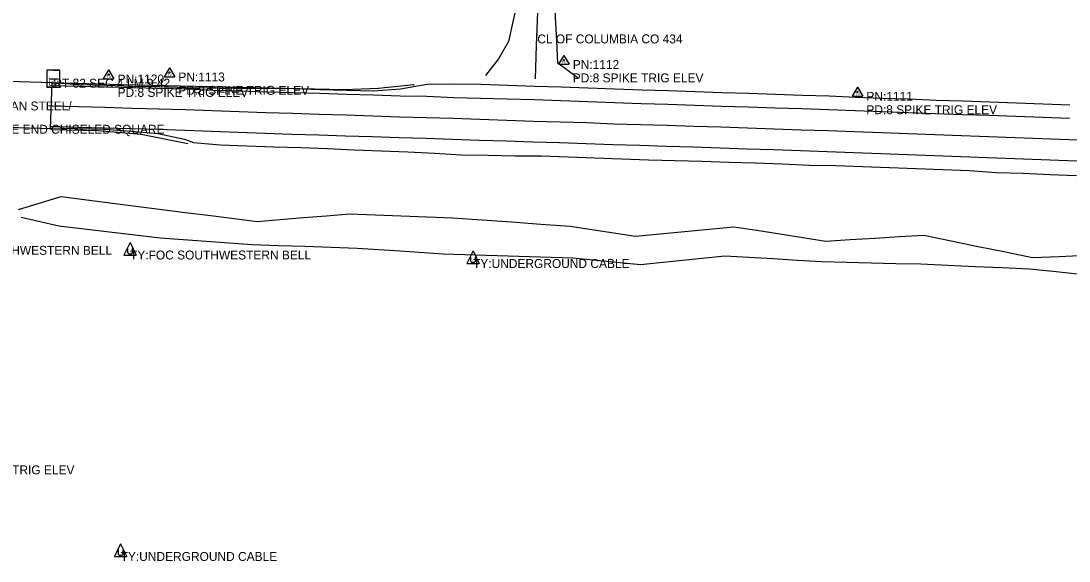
# Model space of a CAD drawing. Extents: x 976456 to 985170, y 1525951 to 1527080.
# Drawn here: x 978069 to 978656, y 1526238 to 1526541 of the extents above; entities that cross this region are included whole.
import ezdxf

# ---------------------------------------------------------------- set-up
doc = ezdxf.new("R2010")
doc.units = 0
for name, color, linetype in [('S_BRIDGE', 7, 'Continuous'), ('S_DITCHLINE', 7, 'Continuous'), ('S_EDGE_PAVEMENT', 7, 'Continuous'), ('S_GRAVEL_ROAD', 7, 'Continuous'), ('S_GUARDRAIL', 7, 'Continuous'), ('S_LOG_MILE', 7, 'Continuous'), ('S_LOG_MILE_ANNOT', 7, 'Continuous'), ('S_MSC_PT_SYM', 7, 'Continuous'), ('S_PAVEMENT_CROWN', 7, 'Continuous'), ('S_PRIMARY_CTL_ANNOT', 7, 'Continuous'), ('S_RDW_PT_SYM', 7, 'Continuous'), ('S_SECONDARY_CTL', 7, 'Continuous'), ('S_SECONDARY_CTL_ANNOT', 7, 'Continuous'), ('S_SHOULDER', 7, 'Continuous'), ('S_STR_PT_SYM', 7, 'Continuous'), ('S_SURVEY_TEXT_ANNOT', 7, 'Continuous'), ('S_UNDERGROUND_CABLE', 7, 'Continuous'), ('S_UTILITY_POLE_ANNOT', 7, 'Continuous')]:
    doc.layers.add(name, color=color, linetype=linetype)

msp = doc.modelspace()

# ---------------------------------------------------------------- linework, layer by layer
at = {"layer": 'S_BRIDGE'}
for p, q in [((978086.33, 1526506.14), (977956.8, 1526510.36)), ((978085.38, 1526480.48), (978086.33, 1526506.14)), ((977955.86, 1526484.94), (978085.38, 1526480.48))]:
    msp.add_line(p, q, dxfattribs=at)
at = {"layer": 'S_DITCHLINE'}
for points in [[(978665.19, 1526409.37), (978650.29, 1526408.71), (978635.4, 1526408.06), (978620.19, 1526411.2), (978604.99, 1526414.35), (978589.78, 1526417.49), (978574.58, 1526420.64), (978560.82, 1526419.8), (978547.07, 1526418.97), (978533.32, 1526418.14), (978519.57, 1526417.3), (978506.68, 1526419.31), (978493.79, 1526421.32), (978480.9, 1526423.33), (978468.01, 1526425.35), (978454.27, 1526424.02), (978440.53, 1526422.7), (978426.8, 1526421.37), (978413.06, 1526420.05), (978394.71, 1526422.87), (978376.37, 1526425.69), (978359.92, 1526426.86), (978343.46, 1526428.03), (978327.01, 1526429.2), (978310.56, 1526430.37), (978296.1, 1526430.93), (978281.65, 1526431.48), (978267.19, 1526432.04), (978252.74, 1526432.59), (978239.84, 1526431.52), (978226.93, 1526430.44), (978214.03, 1526429.36), (978201.13, 1526428.28), (978188.15, 1526429.91), (978175.16, 1526431.55), (978162.18, 1526433.18), (978149.19, 1526434.82), (978134.66, 1526436.69), (978120.12, 1526438.57), (978105.59, 1526440.44), (978091.05, 1526442.31), (978067.19, 1526434.95)], [(978663.72, 1526398.58), (978648.71, 1526400.19), (978633.71, 1526401.8), (978618.47, 1526402.48), (978603.24, 1526403.15), (978588.01, 1526403.82), (978572.78, 1526404.49), (978558.9, 1526404.83), (978545.02, 1526405.17), (978531.15, 1526405.51), (978517.27, 1526405.84), (978503.69, 1526406.65), (978490.12, 1526407.46), (978476.54, 1526408.26), (978462.96, 1526409.06), (978439.36, 1526406.58), (978415.76, 1526404.1), (978396.8, 1526405.97), (978377.85, 1526407.85), (978359.69, 1526408.43), (978341.54, 1526409.01), (978323.38, 1526409.59), (978305.23, 1526410.17), (978281.18, 1526411.77), (978257.12, 1526413.36), (978242.43, 1526413.88), (978227.73, 1526414.39), (978213.04, 1526414.91), (978198.34, 1526415.43), (978185.42, 1526416.34), (978172.5, 1526417.25), (978159.58, 1526418.16), (978146.65, 1526419.07), (978132.48, 1526420.77), (978118.31, 1526422.48), (978104.14, 1526424.18), (978089.97, 1526425.88), (978068.85, 1526430.74)]]:
    msp.add_lwpolyline(points, dxfattribs=at)
at = {"layer": 'S_EDGE_PAVEMENT'}
for points in [[(978086.37, 1526504.73), (978101.36, 1526504.3), (978116.36, 1526503.94), (978131.36, 1526503.46), (978146.36, 1526503.14), (978161.36, 1526502.8), (978176.34, 1526502.14), (978191.34, 1526501.73), (978206.33, 1526501.17), (978221.32, 1526500.71), (978236.19, 1526500.3), (978251.18, 1526499.88), (978266.18, 1526499.47), (978281.17, 1526498.96), (978296.16, 1526498.61), (978311.15, 1526498.02), (978326.18, 1526497.61), (978341.17, 1526497.18), (978356.17, 1526496.74), (978371.16, 1526496.3), (978386.23, 1526495.68), (978401.22, 1526495.14), (978416.21, 1526494.62), (978431.19, 1526494.29), (978446.18, 1526493.67), (978461.17, 1526493.16), (978476.16, 1526492.73), (978491.15, 1526492.23), (978506.14, 1526491.72), (978506.14, 1526491.72), (978521.14, 1526491.22), (978536.12, 1526490.57), (978551.11, 1526490.06), (978566.1, 1526489.56), (978581.09, 1526488.97), (978581.09, 1526488.97), (978596.12, 1526488.42), (978611.12, 1526487.99), (978626.11, 1526487.44), (978641.1, 1526486.88), (978656.09, 1526486.41)], [(978085.55, 1526481.83), (978100.54, 1526481.36), (978115.54, 1526480.97), (978130.52, 1526480.56), (978145.52, 1526480.14), (978145.52, 1526480.14), (978160.51, 1526479.59), (978175.5, 1526479.08), (978190.49, 1526478.52), (978190.49, 1526478.52), (978205.48, 1526477.96), (978220.47, 1526477.44), (978235.56, 1526476.98), (978250.55, 1526476.52), (978265.55, 1526476.07), (978280.54, 1526475.59), (978295.53, 1526475.09), (978310.52, 1526474.56), (978325.49, 1526474.11), (978340.49, 1526473.68), (978355.48, 1526473.18), (978370.47, 1526472.7), (978370.47, 1526472.7), (978385.39, 1526472.21), (978400.38, 1526471.68), (978415.38, 1526471.17), (978430.39, 1526470.66), (978445.38, 1526470.21), (978460.37, 1526469.72), (978475.36, 1526469.25), (978475.36, 1526469.25), (978490.35, 1526468.73), (978505.34, 1526468.18), (978520.34, 1526467.68), (978520.34, 1526467.68), (978535.33, 1526467.17), (978550.32, 1526466.62), (978565.31, 1526466.05), (978580.3, 1526465.46), (978595.25, 1526464.85), (978610.24, 1526464.24), (978625.23, 1526463.76), (978625.23, 1526463.76), (978640.22, 1526463.24), (978640.22, 1526463.24), (978655.21, 1526462.69), (978655.21, 1526462.69), (978670.21, 1526462.19)]]:
    msp.add_lwpolyline(points, dxfattribs=at)
at = {"layer": 'S_GRAVEL_ROAD'}
for points in [[(978361.37, 1526856.47), (978359.38, 1526794.04), (978358.93, 1526780.06), (978358.49, 1526766.07), (978358.04, 1526752.09), (978357.2, 1526736.65), (978356.36, 1526721.22), (978355.52, 1526705.79), (978354.68, 1526690.35), (978354.79, 1526670.11), (978354.9, 1526649.86), (978352.93, 1526629.69), (978350.96, 1526609.51), (978349.95, 1526587.81), (978348.71, 1526571.32), (978347.48, 1526554.83), (978344.69, 1526542.11), (978341.91, 1526529.4), (978336.32, 1526519.7), (978328.9, 1526510.25)], [(978381.06, 1526508.64), (978369.53, 1526517.1), (978368.86, 1526529.94), (978368.19, 1526542.79), (978368.22, 1526555.92), (978368.26, 1526569.05), (978369.23, 1526584.52), (978369.8, 1526604.85), (978370.36, 1526625.19), (978370.83, 1526641.45), (978371.3, 1526657.71), (978371.76, 1526673.97), (978372.23, 1526690.23), (978372.7, 1526702.89), (978373.18, 1526715.55), (978373.65, 1526728.21), (978374.13, 1526740.87), (978374.79, 1526756.83), (978375.46, 1526772.79), (978376.12, 1526788.75), (978378.92, 1526855.74)]]:
    msp.add_lwpolyline(points, dxfattribs=at)
at = {"layer": 'S_GUARDRAIL'}
for p, q in [((978125, 1526505.12), (978086.41, 1526506.23)), ((978249.95, 1526502.28), (978125, 1526505.12)), ((978268.85, 1526502.92), (978249.95, 1526502.28)), ((978288.78, 1526504.99), (978268.85, 1526502.92)), ((978086, 1526480.02), (978111.99, 1526479.4)), ((978111.99, 1526479.4), (978136.01, 1526477.42)), ((978136.01, 1526477.42), (978162.25, 1526472.18))]:
    msp.add_line(p, q, dxfattribs=at)
at = {"layer": 'S_LOG_MILE'}
for p, q in [((978086.9, 1526513.25), (978090.5, 1526513.25)), ((978084.5, 1526508.45), (978089.3, 1526508.45)), ((978086.9, 1526503.65), (978083.3, 1526503.65))]:
    msp.add_line(p, q, dxfattribs=at)
msp.add_lwpolyline([(978090.5, 1526513.25), (978083.3, 1526513.25), (978083.3, 1526503.65), (978090.5, 1526503.65)], close=True, dxfattribs=at)
at = {"layer": 'S_MSC_PT_SYM'}
msp.add_lwpolyline([(978357.98, 1526533.25), (978357.98, 1526533.3), (978357.98, 1526533.25), (978357.93, 1526533.25), (978357.98, 1526533.25), (978357.98, 1526533.2), (978357.98, 1526533.25), (978358.03, 1526533.25)], dxfattribs=at)
at = {"layer": 'S_PAVEMENT_CROWN'}
for points in [[(978356.9, 1526508.47), (978357.57, 1526527.13), (978358.24, 1526545.8), (978359.35, 1526558.49), (978360.47, 1526571.19), (978360.67, 1526585.26), (978361.11, 1526605.62), (978361.56, 1526625.97), (978362.65, 1526642.09), (978363.74, 1526658.21), (978364.83, 1526674.33), (978365.92, 1526690.45), (978366.17, 1526703.09), (978366.42, 1526715.74), (978366.67, 1526728.38), (978366.92, 1526741.02), (978367.64, 1526757.28), (978368.35, 1526773.54), (978369.07, 1526789.8), (978369.78, 1526806.07)], [(978085.96, 1526493.34), (978100.96, 1526492.95), (978115.95, 1526492.5), (978130.94, 1526491.98), (978145.94, 1526491.6), (978160.94, 1526491.22), (978160.94, 1526491.22), (978175.93, 1526490.67), (978175.93, 1526490.67), (978190.92, 1526490.13), (978190.92, 1526490.13), (978205.91, 1526489.6), (978220.9, 1526489.07), (978235.87, 1526488.65), (978250.87, 1526488.15), (978265.86, 1526487.65), (978265.86, 1526487.65), (978280.85, 1526487.19), (978295.84, 1526486.71), (978310.84, 1526486.31), (978310.84, 1526486.31), (978325.83, 1526485.87), (978325.83, 1526485.87), (978340.83, 1526485.33), (978355.82, 1526484.76), (978355.82, 1526484.76), (978370.81, 1526484.32), (978370.81, 1526484.32), (978385.81, 1526483.85), (978385.81, 1526483.85), (978400.8, 1526483.25), (978415.79, 1526482.8), (978415.79, 1526482.8), (978430.79, 1526482.44), (978445.78, 1526481.92), (978445.78, 1526481.92), (978460.77, 1526481.45), (978475.76, 1526480.94), (978475.76, 1526480.94), (978490.75, 1526480.43), (978505.74, 1526479.9), (978520.73, 1526479.39), (978520.73, 1526479.39), (978535.72, 1526478.89), (978550.72, 1526478.38), (978565.71, 1526477.86), (978580.7, 1526477.27), (978595.69, 1526476.72), (978610.68, 1526476.04), (978610.68, 1526476.04), (978625.67, 1526475.53), (978640.66, 1526474.97), (978640.66, 1526474.97), (978655.65, 1526474.42), (978655.65, 1526474.42), (978670.64, 1526473.94)]]:
    msp.add_lwpolyline(points, dxfattribs=at)
at = {"layer": 'S_RDW_PT_SYM'}
for points in [[(978086.41, 1526506.23), (978086.41, 1526506.28), (978086.41, 1526506.23), (978086.36, 1526506.23), (978086.41, 1526506.23), (978086.41, 1526506.18), (978086.41, 1526506.23), (978086.46, 1526506.23)], [(978125, 1526505.12), (978125, 1526505.17), (978125, 1526505.12), (978124.95, 1526505.12), (978125, 1526505.12), (978125, 1526505.07), (978125, 1526505.12), (978125.05, 1526505.12)], [(978249.95, 1526502.28), (978249.95, 1526502.33), (978249.95, 1526502.28), (978249.9, 1526502.28), (978249.95, 1526502.28), (978249.95, 1526502.23), (978249.95, 1526502.28), (978250, 1526502.28)], [(978268.85, 1526502.92), (978268.85, 1526502.97), (978268.85, 1526502.92), (978268.8, 1526502.92), (978268.85, 1526502.92), (978268.85, 1526502.87), (978268.85, 1526502.92), (978268.9, 1526502.92)], [(978288.78, 1526504.99), (978288.78, 1526505.04), (978288.78, 1526504.99), (978288.73, 1526504.99), (978288.78, 1526504.99), (978288.78, 1526504.94), (978288.78, 1526504.99), (978288.83, 1526504.99)], [(978086, 1526480.02), (978086, 1526480.07), (978086, 1526480.02), (978085.95, 1526480.02), (978086, 1526480.02), (978086, 1526479.97), (978086, 1526480.02), (978086.05, 1526480.02)], [(978111.99, 1526479.4), (978111.99, 1526479.45), (978111.99, 1526479.4), (978111.94, 1526479.4), (978111.99, 1526479.4), (978111.99, 1526479.35), (978111.99, 1526479.4), (978112.04, 1526479.4)], [(978136.01, 1526477.42), (978136.01, 1526477.47), (978136.01, 1526477.42), (978135.96, 1526477.42), (978136.01, 1526477.42), (978136.01, 1526477.37), (978136.01, 1526477.42), (978136.06, 1526477.42)], [(978162.25, 1526472.18), (978162.25, 1526472.23), (978162.25, 1526472.18), (978162.2, 1526472.18), (978162.25, 1526472.18), (978162.25, 1526472.13), (978162.25, 1526472.18), (978162.3, 1526472.18)]]:
    msp.add_lwpolyline(points, dxfattribs=at)
at = {"layer": 'S_SECONDARY_CTL'}
for p, q in [((978372.85, 1526521.53), (978369.84, 1526516.57)), ((978372.85, 1526521.53), (978375.79, 1526516.57)), ((978117.88, 1526513.42), (978114.87, 1526508.47)), ((978117.88, 1526513.42), (978120.83, 1526508.47)), ((978151.91, 1526514.56), (978148.9, 1526509.61)), ((978151.91, 1526514.56), (978154.86, 1526509.61)), ((978369.84, 1526516.57), (978375.79, 1526516.57)), ((978114.87, 1526508.47), (978120.83, 1526508.47)), ((978148.9, 1526509.61), (978154.86, 1526509.61)), ((978537.31, 1526503.71), (978534.3, 1526498.75)), ((978537.31, 1526503.71), (978540.26, 1526498.75)), ((978534.3, 1526498.75), (978540.26, 1526498.75))]:
    msp.add_line(p, q, dxfattribs=at)
for centre, radius in [((978372.85, 1526518.92), 0.311), ((978372.85, 1526518.92), 0.183), ((978372.85, 1526518.92), 0.103), ((978117.88, 1526510.81), 0.311), ((978117.88, 1526510.81), 0.183), ((978117.88, 1526510.81), 0.103), ((978151.91, 1526511.95), 0.311), ((978151.91, 1526511.95), 0.183), ((978151.91, 1526511.95), 0.103), ((978537.31, 1526501.1), 0.311), ((978537.31, 1526501.1), 0.183), ((978537.31, 1526501.1), 0.103)]:
    msp.add_circle(centre, radius, dxfattribs=at)
at = {"layer": 'S_SHOULDER'}
for points in [[(978086.43, 1526506.26), (978101.4, 1526505.26), (978116.4, 1526504.89), (978131.4, 1526504.36), (978146.4, 1526504.05), (978161.39, 1526503.6), (978176.4, 1526503.39), (978191.4, 1526503.23), (978206.41, 1526503.21), (978221.41, 1526503.01), (978236.25, 1526502.42), (978251.24, 1526502), (978266.24, 1526501.59), (978281.28, 1526502.85), (978296.35, 1526505.34), (978311.37, 1526505.69), (978326.41, 1526505.35), (978341.4, 1526504.81), (978356.39, 1526504.38), (978371.39, 1526503.94), (978386.51, 1526503.29), (978401.5, 1526502.75), (978416.49, 1526502.18), (978431.45, 1526501.84), (978446.44, 1526501.26), (978461.43, 1526500.77), (978476.43, 1526500.34), (978491.42, 1526499.84), (978506.41, 1526499.33), (978521.4, 1526498.79), (978536.39, 1526498.14), (978551.38, 1526497.63), (978566.37, 1526497.16), (978581.36, 1526496.54), (978596.41, 1526495.99), (978611.4, 1526495.56), (978626.39, 1526494.98), (978641.38, 1526494.37), (978656.37, 1526493.9)], [(978085.51, 1526481.03), (978100.5, 1526480.55), (978115.5, 1526480.14), (978130.46, 1526479.08), (978145.42, 1526477.81), (978160.31, 1526474.55), (978165.4, 1526472.81), (978180.36, 1526471.48), (978195.35, 1526470.84), (978210.34, 1526470.29), (978225.5, 1526469.84), (978240.49, 1526469.39), (978255.48, 1526468.65), (978270.47, 1526468.02), (978285.46, 1526467.51), (978300.44, 1526466.67), (978315.38, 1526465.86), (978330.39, 1526465.66), (978345.38, 1526465.29), (978360.38, 1526465.18), (978375.26, 1526464.78), (978390.24, 1526464.15), (978405.24, 1526463.63), (978420.26, 1526463.09), (978435.26, 1526462.73), (978450.25, 1526462.28), (978465.24, 1526461.76), (978480.23, 1526461.31), (978495.22, 1526460.73), (978510.21, 1526460.05), (978525.21, 1526459.79), (978540.2, 1526459.34), (978555.19, 1526458.77), (978570.18, 1526458.21), (978585.12, 1526457.67), (978600.1, 1526457.01), (978615.08, 1526455.98), (978630.07, 1526455.58), (978645.05, 1526454.87), (978660.04, 1526454.15)]]:
    msp.add_lwpolyline(points, dxfattribs=at)
at = {"layer": 'S_STR_PT_SYM'}
for points in [[(978086.33, 1526506.14), (978086.33, 1526506.64), (978086.33, 1526506.14), (978085.83, 1526506.14), (978086.33, 1526506.14), (978086.33, 1526505.64), (978086.33, 1526506.14), (978086.83, 1526506.14)], [(978085.38, 1526480.48), (978085.38, 1526480.98), (978085.38, 1526480.48), (978084.88, 1526480.48), (978085.38, 1526480.48), (978085.38, 1526479.98), (978085.38, 1526480.48), (978085.88, 1526480.48)]]:
    msp.add_lwpolyline(points, dxfattribs=at)
at = {"layer": 'S_UNDERGROUND_CABLE'}
for p, q in [((978129.86, 1526416.73), (978126.34, 1526409.64)), ((978128.66, 1526410.88), (978128.66, 1526413.32)), ((978129.86, 1526416.73), (978133.35, 1526409.64)), ((978131.03, 1526413.32), (978131.03, 1526410.88)), ((978126.34, 1526409.64), (978133.35, 1526409.64)), ((978129.28, 1526410.22), (978128.66, 1526410.88)), ((978130.48, 1526410.22), (978129.28, 1526410.22)), ((978131.03, 1526410.88), (978130.48, 1526410.22)), ((978321.98, 1526411.94), (978318.45, 1526404.85)), ((978320.78, 1526406.09), (978320.78, 1526408.53)), ((978321.98, 1526411.94), (978325.46, 1526404.85)), ((978323.14, 1526408.53), (978323.14, 1526406.09)), ((978318.45, 1526404.85), (978325.46, 1526404.85)), ((978321.4, 1526405.43), (978320.78, 1526406.09)), ((978322.6, 1526405.43), (978321.4, 1526405.43)), ((978323.14, 1526406.09), (978322.6, 1526405.43)), ((978124.6, 1526247.81), (978121.08, 1526240.72)), ((978123.4, 1526241.96), (978123.4, 1526244.4)), ((978124.6, 1526247.81), (978128.09, 1526240.72)), ((978125.77, 1526244.4), (978125.77, 1526241.96)), ((978121.08, 1526240.72), (978128.09, 1526240.72)), ((978124.02, 1526241.3), (978123.4, 1526241.96)), ((978125.22, 1526241.3), (978124.02, 1526241.3)), ((978125.77, 1526241.96), (978125.22, 1526241.3))]:
    msp.add_line(p, q, dxfattribs=at)

# ---------------------------------------------------------------- texts
at = {"layer": 'S_LOG_MILE'}
msp.add_text('LM', height=3, rotation=360, dxfattribs=at).set_placement((978084.36, 1526504.61))
at = {"layer": 'S_LOG_MILE_ANNOT'}
msp.add_text('RT 82 SEC 4 LM 9.42', height=5, dxfattribs=at).set_placement((978086.9, 1526503.45))
at = {"layer": 'S_PRIMARY_CTL_ANNOT'}
msp.add_text('PD:CONCRETE BRIDGE END CHISELED SQUARE', height=5, dxfattribs=at).set_placement((977991.67, 1526477.63))
at = {"layer": 'S_SECONDARY_CTL'}
for p in [(978371.64, 1526516.9), (978116.68, 1526508.8), (978150.71, 1526509.94), (978536.11, 1526499.09)]:
    msp.add_text('TV', height=1.5, rotation=360, dxfattribs=at).set_placement(p)
at = {"layer": 'S_SECONDARY_CTL_ANNOT'}
for s, p in [('PN:1112', (978377.85, 1526513.92)), ('PN:1120', (978122.88, 1526505.81)), ('PN:1113', (978156.92, 1526506.95)), ('PD:8 SPIKE TRIG ELEV', (978377.85, 1526506.42)), ('PD:8 SPIKE TRIG ELEV', (978122.88, 1526498.31)), ('PD:8 SPIKE TRIG ELEV', (978156.92, 1526499.45)), ('PN:1111', (978542.31, 1526496.1)), ('PD:8 SPIKE TRIG ELEV', (978542.31, 1526488.6)), ('PD:8 SPIKE TRIG ELEV', (978025.53, 1526286.8))]:
    msp.add_text(s, height=5, dxfattribs=at).set_placement(p)
at = {"layer": 'S_SURVEY_TEXT_ANNOT'}
for s, p in [('CL OF COLUMBIA CO 434', (978357.98, 1526528.25)), ('BR 2667 4 SPAN STEEL/', (978020.61, 1526490.7))]:
    msp.add_text(s, height=5, dxfattribs=at).set_placement(p)
at = {"layer": 'S_UTILITY_POLE_ANNOT'}
for s, p in [('TY:FOC SOUTHWESTERN BELL', (978018.37, 1526409.8)), ('TY:FOC SOUTHWESTERN BELL', (978129.86, 1526407.19)), ('TY:UNDERGROUND CABLE', (978321.98, 1526402.41)), ('TY:UNDERGROUND CABLE', (978124.6, 1526238.27))]:
    msp.add_text(s, height=5, dxfattribs=at).set_placement(p)

doc.saveas('drawing.dxf')
